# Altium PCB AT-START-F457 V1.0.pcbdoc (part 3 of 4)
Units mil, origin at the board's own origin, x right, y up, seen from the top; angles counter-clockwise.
Board outline 11593.57 x 3554 mil, 2 copper layers (Top Layer, Bottom Layer); 196 components, 231 nets, 905 pads, 932 vias.
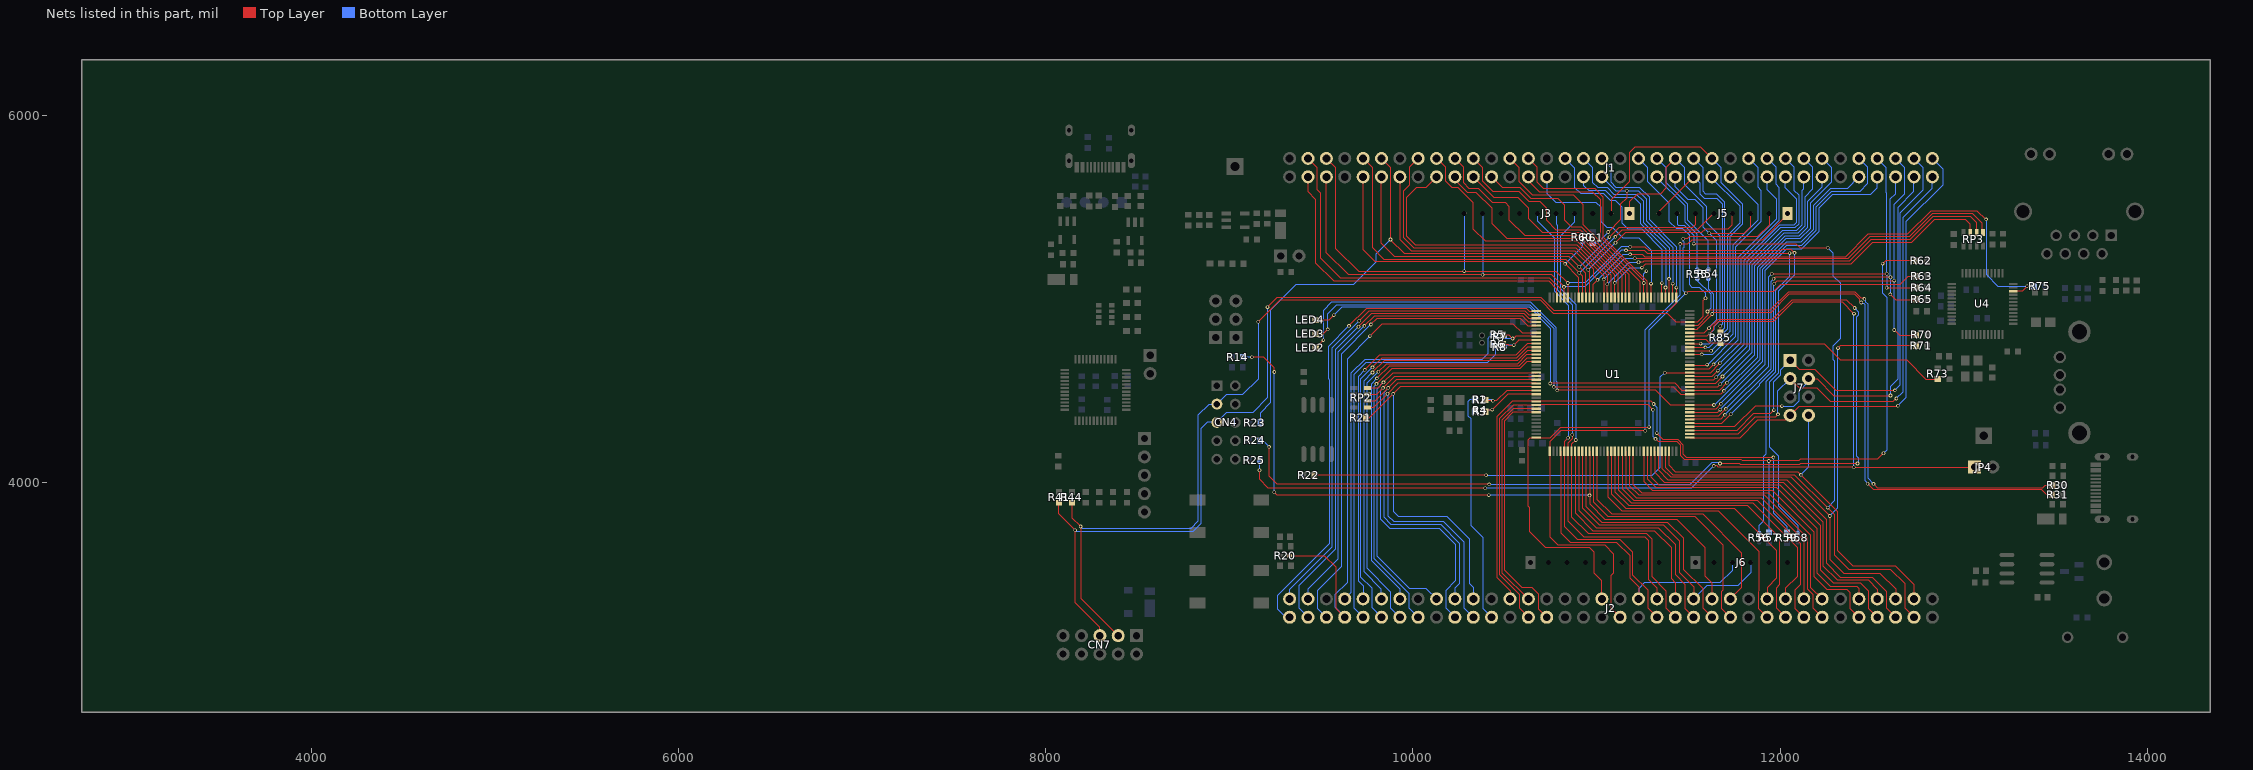
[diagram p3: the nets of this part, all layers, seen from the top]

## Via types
v1: diameter 19.7, hole 11.8, Top Layer to Bottom Layer, 489 vias
v2: diameter 19.68, hole 11.81, Top Layer to Bottom Layer, 425 vias
v3: diameter 31.5, hole 19.68, Top Layer to Bottom Layer, 18 vias

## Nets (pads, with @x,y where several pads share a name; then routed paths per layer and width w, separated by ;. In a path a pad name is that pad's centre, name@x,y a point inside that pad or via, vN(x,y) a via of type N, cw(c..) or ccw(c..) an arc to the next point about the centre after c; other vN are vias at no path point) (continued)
PA2: J2.36 J5.2 R63.1 U1.36 | length 4831.4
  Top Layer w6: J2.36@11029.17,3367.08 11029.16,3466.98 10988.26,3507.98 10988.26,3619.98 10962.26,3645.98 10723.16,3645.98 10637.36,3731.78 10637.36,3862.08 10628.51,3870.93 10628.51,4233.83 10640.16,4245.48 U1.36@10671.86,4245.5 10748.11,4245.48 10804.61,4301.98 11286.38,4301.98 v2(11286.92,4302.51) ; v2(11472.46,5327.97) 11493.46,5327.97 11504.98,5339.49 11876.37,5339.49 11939.76,5402.88 J5.2@11939.8,5465.97 ; v2(11487.2,5031.73) 11499.08,5043.61 11966.25,5043.61 12003.14,5080.5 12654.81,5080.5 12698.19,5123.88 R63.1@12741.42,5123.88
  Bottom Layer w6: v2(11286.92,4302.51) 11286.92,4832.35 11486.29,5031.73 v2(11487.2,5031.73) 11474.03,5044.89 11474.03,5279.85 11477.58,5283.4 11477.58,5308.44 11474.03,5311.99 11474.03,5326.4 v2(11472.46,5327.97)
PA3: J2.37 J5.1 U1.37 | length 3573.7
  Top Layer w6: J2.37@11129.17,3267.08 11078.26,3318.08 11078.26,3493.98 11092.26,3507.98 11092.26,3613.88 11043.96,3662.18 10789.96,3662.18 10745.76,3706.38 10745.76,4171.68 10745.76,4222.64 10805.43,4282.31 v2(11265.79,4282.31) ; v2@11455.95,5300.35 11497.63,5300.35 11520.43,5323.15 11904.31,5323.15 12039.76,5458.69 J5.1@12039.8,5465.97
  Bottom Layer w6: v2(11265.79,4282.31) 11265.79,4832.84 11456.7,5023.74 11456.7,5299.6 v2(11455.91,5300.39)
PA4: J2.40 J6.3 U1.40 | length 1779.9
  Top Layer w6: U1.40@10804.76,4171.68 10804.76,3728.38 10856.46,3676.68 11108.56,3676.68 11180.26,3604.98 11180.26,3481.18 11229.16,3432.28 J2.40@11229.17,3367.08
  Bottom Layer w6: J2.40@11229.17,3367.08 11229.16,3422.98 11260.26,3453.98 11672.26,3453.98 11739.86,3521.58 J6.3@11739.86,3565.98
PA5: J2.41 J3.6 U1.41 | length 2624.8
  Top Layer w6: v2(10845.74,4244.57) 10845.74,4243.88 10824.46,4222.6 10824.46,4171.68 10824.46,3761.68 10895.26,3690.98 11128.16,3690.98 11196.26,3622.98 11196.26,3497.98 11278.26,3415.98 11278.26,3318.08 J2.41@11329.17,3267.08
  Bottom Layer w6: J3.6@10679.86,5465.98 10679.86,5424.38 10772.26,5331.98 10772.26,5041.78 10849.23,4964.8 10849.23,4248.06 v2(10845.74,4244.57)
PA6: J2.42 J3.5 U1.42 | length 2540.2
  Top Layer w6: v2(10868.07,4261.17) 10868.07,4238.25 10844.16,4214.33 10844.16,4171.68 10844.16,3792.98 10931.26,3705.98 11262.26,3705.98 11282.26,3685.98 11282.26,3474.88 11329.16,3427.98 J2.42@11329.17,3367.08
  Bottom Layer w6: J3.5@10779.86,5465.98 10779.86,5409.38 10787.26,5401.98 10787.26,5049.37 10868.07,4968.55 v2(10868.07,4261.17)
PA7: J2.43 J3.4 U1.43 | length 2695.5
  Top Layer w6: v2(10886.92,4232.13) 10886.38,4232.13 10863.86,4209.61 10863.86,4171.68 10863.86,3814.88 10954.76,3723.98 11271.26,3723.98 11300.26,3694.98 11300.26,3489.98 11378.26,3411.98 11378.26,3318.08 J2.43@11429.17,3267.08
  Bottom Layer w6: J3.4@10879.86,5465.98 10879.86,5419.38 10802.26,5341.78 10802.26,5057.48 10886.92,4972.82 v2(10886.92,4232.13)
PA8: R73.1 R85.2 U1.100 | length 1438.4
  Top Layer w6: U1.100@11508.56,4776.98 11598.72,4776.98 11616.38,4759.32 R85.2@11675.37,4759.32 11678.8,4755.88 12240.28,4755.88 12327.55,4668.61 12688.93,4668.61 12793.39,4564.15 R73.1@12858.77,4564.15
PA8_E: J1.28 J5.8 R85.1 | length 1234.4
  Top Layer w6: J5.8@11339.8,5465.97 11339.76,5476.28 J1.28@11529.16,5665.68 ; v2(11674.65,4852.07) 11674.65,4819.36 R85.1@11675.37,4818.64
  Bottom Layer w6: J1.28@11529.16,5665.68 11562.68,5632.15 11562.68,5573.01 11585.76,5549.98 11654.26,5549.98 11684.86,5519.38 11684.86,4862.28 v2(11674.65,4852.07)
PA9: J1.29 J3.1 JP4.1 R25.2 U1.101 | length 7470.9
  Top Layer w6: v2@9165.26,4067.98 9165.26,4017.48 9213.04,3969.7 v2(10394.29,3969.7) ; J3.1@11179.86,5465.98 11179.86,5529.58 11222.26,5571.98 11346.26,5571.98 11378.26,5603.98 11378.26,5714.68 J1.29@11429.16,5765.68 ; U1.101@11508.56,4796.68 11601.67,4796.68 v2(11616.51,4811.52) 11637.11,4832.12 11637.11,4848.16 11664.43,4875.48 11962.39,4875.48 12069.05,4982.14 12340.98,4982.14 v2(12402.52,4920.6) ; v2(11638.56,4091.12) 11657.79,4091.12 11664,4084.9 12097.95,4084.9 12098.24,4084.61 12402.59,4084.61 v1(12401.55,4083.57) 13057.26,4083.57 JP4.1@13058.9,4085.21
  Bottom Layer w5.98: v2(11616.51,4811.52) 11637.75,4832.76
  Bottom Layer w6: R25.2@9165.16,4123.08 9165.16,4068.18 v2@9165.26,4067.98 ; v2(10394.29,3969.7) 11517.14,3969.7 v2(11638.56,4091.12) ; J1.29@11429.16,5765.68 11430.23,5765.68 11478.47,5717.43 11478.47,5625.23 11598.47,5505.23 11598.47,5417.73 11670.47,5345.73 11670.47,4881.96 11637.75,4849.24 11637.75,4832.76 ; v1(12401.55,4083.57) 12401.6,4919.67 v2(12402.52,4920.6)
  other v2: 9165.21,4067.97
PA10: J1.30 J5.3 R24.2 U1.102 | length 6628.5
  Top Layer w5.98: v2(11672.93,4104.54) 11778.61,4104.54 11784.06,4099.09
  Top Layer w6: v2(9217.21,4194.97) 9217.21,4034.97 9261.35,3990.83 v2(10415.89,3990.83) ; U1.102@11508.56,4816.38 11588.38,4816.38 v2(11612.86,4840.85) 11659.48,4887.48 11955.7,4887.48 12062.26,4994.12 12363.24,4994.12 v2(12406.02,4951.35) ; v2(11614.7,5358.7) 11803.86,5358.68 11839.76,5394.68 J5.3@11839.8,5465.97 ; 11784.06,4099.09 12106.71,4099.09 12112.23,4104.61 v1(12421.75,4104.61)
  Bottom Layer w6: R24.2@9165.76,4229.98 9182.16,4229.98 v2@9217.26,4194.98 ; v2(10415.89,3990.83) 11510.33,3990.83 11630.02,4110.51 11666.95,4110.51 v2(11672.93,4104.54) ; J1.30@11429.16,5665.68 11429.16,5612.78 11501.26,5540.78 11537.86,5540.78 11581.56,5496.98 11581.56,5391.78 v2(11614.7,5358.7) ; v2(11612.86,4840.85) 11612.86,4843.5 11655.27,4885.91 11655.27,5318.12 v2(11614.7,5358.7) ; v2(12406.02,4951.35) 12425.85,4931.51 12425.85,4911.76 12415.25,4901.16 12415.25,4147.35 12425.85,4136.75 12425.85,4108.71 v1(12421.75,4104.61)
PA11: R31.1 R54.2 U1.103 | length 3282.1
  Top Layer w5.98: v2(12476.65,3994.46) 12510.5,3960.61 13424.57,3960.61 13451.57,3933.61 R31.1@13481.91,3933.61
  Top Layer w6: U1.103@11508.48,4836.05 11548.07,4836.05 11555.72,4843.7 11555.94,4843.7 11616.54,4904.3 11616.54,4904.52 v2(11630.42,4918.4) 11638.33,4926.31 11948.84,4926.31 12047.91,5025.38 12406.09,5025.38 12433.82,4997.65 12433.82,4989.16 v2@12441.74,4981.24
  Bottom Layer w6: R54.2@11609.4,5114.26 11609.4,5057.08 11636.57,5029.91 11636.57,4924.55 v2(11630.42,4918.4) ; v2(12441.7,4981.25) 12447.61,4975.34 12457.29,4975.34 12464.22,4968.4 12464.22,4009.93 12476.65,3997.5 v2(12476.65,3994.46)
PA11_E: J1.31 R54.1 | length 726
  Bottom Layer w6: J1.31@11329.16,5765.68 11380.26,5714.58 11380.26,5633.98 11497.66,5516.58 11497.66,5429.28 11608.26,5318.68 R54.1@11608.26,5155.28
PA12: R30.1 R55.2 U1.104 | length 3293.1
  Top Layer w5.98: U1.104@11508.56,4855.68 11550.98,4855.68 11604.56,4909.27 11604.56,4909.48 11604.85,4909.76 v2(11604.85,4932.15) ; v2(12508.84,3993.3) 12529.56,3972.58 13431.54,3972.58 13444.57,3985.61 R30.1@13482.91,3985.61
  Top Layer w6: v2(11604.85,4932.15) 11612.01,4939.31 11944.9,4939.31 12043.64,5038.06 12410.38,5038.06 12443.15,5005.29 12454.65,5005.29 v2@12459.03,5000.9
  Bottom Layer w6: R55.2@11549.03,5099.37 R55.2@11549.03,5100.5 ; R55.2@11549.03,5113.47 R55.2@11549.03,5100.5 ; v2(11604.85,4932.15) 11624.58,4951.89 11624.58,5024.95 R55.2@11549.03,5100.5 ; v2(12459.03,5000.95) 12465.03,4994.95 12465.03,4984.56 12476.22,4973.37 12476.22,4025.51 12508.43,3993.3 v2(12508.84,3993.3)
PA12_E: J1.32 R55.1 | length 601.9
  Bottom Layer w6: J1.32@11329.16,5665.68 11329.16,5660.98 11483.06,5507.08 11483.06,5418.98 11550.16,5351.88 R55.1@11550.16,5155.28
PA13/SWDIO: CN4.3 CN7.3 J1.33 R44.2 U1.105 | length 6379.1
  Top Layer w6: R44.2@8144.46,3888.68 8144.46,3807.38 v2(8190.46,3761.38) 8190.46,3371.66 CN7.3@8395.46,3166.58 ; v2@9158.26,4875.98 9277.17,4994.9 10692.84,4994.9 10764.76,4922.98 11385.27,4922.98 11432.77,4875.38 U1.105@11508.48,4875.42 11550.89,4875.38 11582.58,4907.07 11582.58,4992.55 v2(11593.93,5003.91)
  Bottom Layer w6: v2(8190.46,3761.38) 8199.22,3752.61 8793.57,3752.61 8832.26,3791.3 8832.26,4368.88 8891.53,4428.15 CN4.3@8933.23,4427.98 ; CN4.3@8933.26,4427.98 8970.96,4466.28 8983.16,4477.68 9072.16,4477.68 9158.26,4563.78 v2@9158.26,4875.98 ; J1.33@11229.16,5765.68 11280.26,5714.58 11280.26,5639.18 11397.56,5521.88 11397.56,5422.18 11436.26,5383.48 11470.86,5383.48 11506.76,5347.68 11506.76,5078.43 11522.46,5062.72 11563.62,5062.72 11593.93,5032.4 v2(11593.93,5003.91)
  other v2: 9158.21,4875.97
PA14/SWCLK: CN4.5 CN7.5 J1.37 R41.2 U1.109 | length 6292.3
  Top Layer w6: R41.2@8070.46,3888.68 8070.46,3830.78 v2(8160.56,3740.58) 8161.97,3739.27 8161.97,3346.21 8295.46,3212.73 CN7.5@8295.46,3166.58 ; v2@9208.26,4955.98 9259.16,5006.88 10699.46,5006.88 10771.36,4934.98 11393.48,4934.98 11434.66,4976.15 U1.109@11434.66,5008.31 11435.16,5008.78 v2(11435.21,5061.97)
  Bottom Layer w6: v2(8160.56,3740.58) 8168.52,3732.61 8801.57,3732.61 8845.26,3776.3 8845.26,4294.08 8879.26,4328.18 ; 8880.73,4327.97 CN4.5@8933.23,4327.98 8933.23,4330.45 8984.76,4381.98 9126.96,4381.98 9208.26,4463.28 v2@9208.26,4955.98 ; J1.37@11029.16,5765.68 11078.26,5716.58 11078.26,5637.88 11106.16,5609.98 11234.26,5609.98 11286.26,5557.98 11286.26,5434.58 11435.16,5285.68 v2(11435.21,5061.97)
  other v2: 9208.21,4955.97
PA15: J1.38 R61.1 U1.110 | length 1263.8
  Top Layer w6: v2(11063.88,5365.01) 11130.86,5431.98 11130.86,5515.88 11164.96,5550.08 v2(11165,5589.98) ; U1.110@11414.97,5008.31 11415.16,5008.48 v2(11415.21,5083.97)
  Bottom Layer w6: R61.1@10979.26,5307.48 11006.36,5307.48 v2(11063.88,5365.01) ; J1.38@11029.16,5665.68 11104.86,5589.98 v2(11165,5589.98) ; v2(11165,5589.98) 11226.26,5589.98 11270.26,5545.98 11270.26,5426.18 11415.16,5281.28 v2(11415.21,5083.97)
PB0: J2.46 J6.4 U1.46 | length 1685.8
  Top Layer w6: U1.46@10922.86,4171.68 10922.86,3862.28 11014.66,3770.48 11362.76,3770.48 11449.96,3683.28 11449.96,3513.18 11529.16,3434.08 J2.46@11529.17,3367.08
  Bottom Layer w6: J2.46@11529.17,3367.08 11600.06,3437.98 11768.26,3437.98 11839.86,3509.58 J6.4@11839.86,3565.98
PB1: J2.47 U1.47 | length 1397.4
  Top Layer w6: U1.47@10942.56,4171.68 10942.56,3872.88 11029.96,3785.48 11385.76,3785.48 11472.46,3698.78 11472.46,3529.78 11578.26,3423.98 11578.26,3318.08 J2.47@11629.17,3267.08
PB2/BOOT1: J2.48 R14.2 U1.48 | length 3908.9
  Top Layer w6: v2@9123.26,4682.98 9188.46,4682.98 9245.96,4625.48 v2@9245.96,4602.58 ; v2(9245.65,3947.99) 9261.67,3931.97 v2(10413.21,3931.97) ; U1.48@10962.26,4171.68 U1.48@10962.22,4171.68 v2(10962.21,3930.97) 10962.16,3883.98 11046.06,3800.08 11438.06,3800.08 11590.26,3647.88 11590.26,3493.88 11629.16,3454.98 J2.48@11629.17,3367.08
  Bottom Layer w6: R14.2@9072.76,4683.98 v2@9123.26,4682.98 ; v2(9245.65,3947.99) 9245.95,3948.29 v2(9245.95,4602.58) ; v2(10413.21,3931.97) 10414.21,3930.97 v2(10962.21,3930.97)
  other v2: 9123.21,4682.97
PB3: J1.61 J5.4 R23.2 U1.133 | length 4184.6
  Top Layer w6: J1.61@9829.16,5765.68 9878.26,5716.58 9878.26,5323.98 9952.26,5249.98 10865.2,5249.98 v2@10955.55,5159.63 ; v2@10955.56,5159.58 10962.26,5152.98 U1.133@10962.26,5008.28 ; v2(11103.68,5306.7) 11160.02,5363.04 11574.1,5363.04 11594.16,5383.18 11719.06,5383.18 11739.76,5403.78 J5.4@11739.8,5465.97
  Bottom Layer w6: R23.2@9167.76,4326.18 9167.66,4377.58 9223.86,4433.98 9223.86,4937.71 9363.38,5077.23 9676.13,5077.23 9798.08,5199.18 9798.08,5244 v2@9878.26,5324.18 ; v2@10955.55,5159.63 11102.62,5306.7 v2(11103.68,5306.7)
  other v2: 10955.55,5159.63 9878.21,5323.97
PB4: J1.62 J5.6 U1.134 | length 2465.4
  Top Layer w6: J1.62@9829.16,5665.68 9826.26,5662.68 9826.26,5305.98 9898.26,5233.98 10848.19,5233.98 v2(10906.68,5175.49) 10942.2,5139.97 ; 10942.16,5139.98 10942.16,5008.68 U1.134@10942.56,5008.28 ; v2(11070.58,5337.43) 11124.16,5390.98 11523.66,5390.98 11539.76,5407.08 J5.6@11539.8,5465.97
  Bottom Layer w6: v2(10906.68,5175.49) 10908.64,5175.49 v2(11070.58,5337.43)
PB5: J1.63 J5.5 U1.135 | length 2698.3
  Top Layer w6: J1.63@9729.16,5765.68 9778.26,5716.58 9778.26,5281.98 9842.26,5217.98 10831.74,5217.98 v2(10906.75,5143) 10922.86,5126.86 U1.135@10922.86,5008.28 ; v2(11102.89,5338.22) 11140.76,5376.08 11549.86,5376.08 J5.5@11639.8,5465.97
  Bottom Layer w6: v2(10906.75,5143) 10907.67,5143 v2(11102.89,5338.22)
PB6: J1.64 R60.2 U1.136 | length 1904.4
  Top Layer w6: J1.64@9729.16,5665.68 9729.16,5269.08 9796.26,5201.98 10818.5,5201.98 v2(10829.24,5191.23) 10903.16,5117.32 U1.136@10903.16,5008.31
  Bottom Layer w5.98: 10923.85,5285.84 R60.2@10923.85,5313.9
  Bottom Layer w6: v2(10829.24,5191.23) 10923.85,5285.84
PB8: J1.67 J3.10 R58.1 U1.139 | length 5231.9
  Top Layer w6: J1.67@9529.16,5765.18 9578.26,5716.58 9578.26,5277.88 9704.26,5151.98 v2(10280.21,5151.97) 10779.16,5151.98 v2@10843.52,5087.62 ; v2(10843.58,5087.62) 10843.56,5008.78 U1.139@10844.16,5008.18 ; v2@11184.27,5284.97 11264.36,5284.97 11284.65,5264.68 12003.86,5264.68 12010.9,5271.73 12058.02,5271.73 v2(12078.36,5251.39)
  Bottom Layer w5.98: v2(12078.36,5251.39) 12078.36,5130.48 11989.23,5041.35 11989.23,4595.16 11941.65,4547.59 11941.65,4194.26 11989.23,4146.69 11989.23,3874.73 12096.95,3767 R58.1@12096.95,3722.29
  Bottom Layer w6: J3.10@10279.86,5465.98 10279.86,5394.38 10280.16,5394.08 v2(10280.21,5151.97) ; v2(10843.58,5087.62) 10938.81,5087.62 11136.16,5284.98 v2@11184.26,5284.98
  other v2: 11184.21,5284.97
PB9: J1.68 J3.9 R56.1 U1.140 | length 5089.1
  Top Layer w6: J1.68@9529.16,5665.18 9529.16,5252.98 9650.26,5131.98 v2(10379.81,5131.97) 10757.26,5131.98 10823.26,5065.98 10823.26,5009.38 U1.140@10824.46,5008.18 ; v2(11161.21,5264.97) 11261.21,5264.97 11275.9,5250.28 v2(12051.95,5250.28)
  Bottom Layer w5.98: R56.1@11886.22,3723.08 11886.54,3723.4 11886.54,3768.6 11909.85,3791.92 11909.85,4142.52 11925.68,4158.34 11925.68,4552.87 11977.12,4604.31 11977.12,5048.7 12051.95,5123.53 v2(12051.95,5250.28)
  Bottom Layer w6: v2@10379.86,5131.98 J3.9@10379.86,5465.98 ; v2(10823.21,5065.97) 10937.34,5065.97 11136.34,5264.97 v2(11161.21,5264.97)
PB10: J2.69 J5.7 U1.69 | length 4423.2
  Top Layer w6: U1.69@11375.66,4171.68 11375.66,4085.08 11416.86,4043.98 12078.36,4043.98 v2@12258.76,3863.58 ; v2(11529.8,5301.63) 12086.6,5301.63 12109.27,5278.96 v2(12259.62,5278.96) ; v2(12259.51,3864.33) v2@12258.76,3863.58 ; J2.69@12729.17,3267.08 12678.26,3318.08 12678.26,3450.88 12600.66,3528.58 12373.6,3528.58 12293.72,3608.47 12293.72,3828.62 v2@12258.76,3863.58
  Bottom Layer w6: J5.7@11439.8,5465.97 11439.76,5407.48 11446.06,5401.28 11477.16,5401.28 11529.8,5348.64 v2(11529.8,5301.63) ; v2(12259.51,3864.33) 12295.87,3900.69 12295.87,4664.78 12287.41,4673.23 12287.41,4743.57 12326.75,4782.9 12326.75,5087.69 12287.41,5127.02 12287.41,5251.17 v2(12259.62,5278.96)
PB11: J2.70 J7.8 U1.70 | length 2245.9
  Top Layer w6: U1.70@11395.36,4171.68 11395.36,4094.98 11433.06,4057.28 11954.13,4057.28 11954.57,4057.72 12098.12,4057.72 ; v1(12113.57,4042.61) 12098.47,4057.72 12098.12,4057.72 ; J2.70@12729.17,3367.08 12729.16,3447.28 12627.76,3548.68 12395.86,3548.68 12312.19,3632.34 12312.19,3843.64 12098.12,4057.72
  Bottom Layer w6: v1(12113.57,4042.61) 12154.81,4083.85 J7.8@12154.81,4366.56
PB12: J1.1 J7.7 U1.73 | length 2676.8
  Top Layer w6: U1.73@11508.48,4245.5 11782.52,4245.5 11878.99,4341.98 12030.22,4341.98 J7.7@12054.81,4366.56 12104.86,4416.61 12639.57,4416.61 v1(12641.57,4418.61)
  Bottom Layer w6: v1(12641.57,4418.61) 12685.5,4462.54 12685.5,5419.63 12886.26,5620.48 12886.26,5708.58 J1.1@12829.16,5765.68
PB13: J1.2 J7.3 U1.74 | length 2671.3
  Top Layer w6: U1.74@11508.48,4265.19 11772.67,4265.19 11865.87,4358.39 11975.22,4358.39 v1(11988.45,4371.61) ; J7.3@12054.81,4566.56 12104.75,4516.61 12199.57,4516.61 12273.57,4442.61 12617.57,4442.61 v1(12633.57,4458.61)
  Bottom Layer w5.98: v1(11988.45,4371.61) 11988.45,4500.2 J7.3@12054.81,4566.56
  Bottom Layer w6: v1(12633.57,4458.61) 12670.36,4495.4 12670.36,5444.78 12829.16,5603.58 J1.2@12829.16,5665.68
PB14: J1.3 J7.1 U1.75 | length 2797.8
  Top Layer w6: U1.75@11508.48,4284.87 11765.61,4284.87 11857.95,4377.21 11948.58,4377.21 v1(11966.35,4394.98) ; J7.1@12054.81,4666.56 12104.75,4616.61 12189.83,4616.61 12303.83,4502.61 v1(12625.57,4502.61)
  Bottom Layer w6: v1(11966.35,4394.98) 11966.35,4550.36 12004.19,4588.19 12004.19,4615.55 12054.81,4666.17 J7.1@12054.81,4666.56 ; v1(12625.57,4502.61) 12655.22,4532.26 12655.22,5470.54 12779.26,5594.58 12779.26,5715.58 J1.3@12729.16,5765.68
PB15: J1.4 J7.4 U1.76 | length 2524
  Top Layer w6: U1.76@11508.48,4304.56 11751.22,4304.56 11863.52,4416.86 v1(12010.14,4416.86) ; J7.4@12154.81,4566.56 12201.62,4566.56 12293.57,4474.61 v1(12601.57,4474.61)
  Bottom Layer w6: v1(12010.14,4416.86) 12031.33,4416.86 12031.57,4416.61 12073.57,4416.61 12103.57,4446.61 12103.57,4498.61 12154.81,4549.85 J7.4@12154.81,4566.56 ; v1(12601.57,4474.61) 12601.57,4525.12 12642.56,4566.11 12642.56,5500.42 12729.16,5587.08 J1.4@12729.16,5665.68
PC0: J2.26 R59.1 U1.26 | length 3240.4
  Top Layer w6: J2.26@10529.17,3367.08 10530.26,3368.08 10530.26,3411.93 10458.26,3483.93 10458.26,4359.3 10541.23,4442.28 U1.26@10671.86,4442.35 11297.51,4442.28 v2(11311.47,4428.32) ; v2(11328.21,4269.97) 11328.21,4267.98 11359.92,4236.27 11441.97,4236.27 11470.48,4207.75 11470.48,4157.41 11489.79,4138.09 11962.99,4138.09 v2(11963.64,4137.44)
  Bottom Layer w6: v2(11311.47,4428.32) 11328.21,4411.59 v2(11328.21,4269.97) ; v2(11963.64,4137.44) 11963.64,3835.3 12037.06,3761.88 R59.1@12037.06,3729.62
PC1: J2.27 R57.1 R62.1 U1.27 | length 5163
  Top Layer w6: J2.27@10629.17,3267.08 10578.26,3318.08 10578.26,3391.93 10470.26,3499.93 10470.26,4347.3 10545.63,4422.68 U1.27@10671.86,4422.67 10672.26,4422.98 11281.24,4422.98 v2(11307.17,4397.05) ; v2(11321.68,4238.22) 11338.34,4221.56 11439.72,4221.56 11458.49,4202.79 11458.49,4146.15 11480.41,4124.23 11789.72,4124.23 11795.98,4117.98 v2(11938.17,4118) 12100.87,4117.98 12109.56,4126.67 12529.56,4126.67 v2(12563.05,4160.16) ; v2(12558.37,5193.11) 12574.35,5209.08 R62.1@12740.55,5209.08
  Bottom Layer w6: v2(11307.17,4397.05) 11307.21,4252.7 v2(11321.68,4238.22) ; v2(11938.17,4118) 11938.22,3729.42 R57.1@11940.16,3727.48 ; v2(12558.37,5193.11) 12558.37,5032.43 12582.74,5008.07 12582.74,4179.84 v2(12563.05,4160.16)
PC2: J2.28 U1.28 | length 1245.1
  Top Layer w6: J2.28@10629.1,3367.08 10485.57,3510.61 10485.57,4340.61 10547.93,4402.98 U1.28@10671.86,4402.98
PC3: J2.29 U1.29 | length 1390.1
  Top Layer w6: U1.29@10671.86,4383.3 10545.2,4383.28 10497.57,4335.64 10497.57,3526.61 10593.57,3430.61 10647.66,3430.61 10682.26,3395.89 10682.26,3314.08 J2.29@10729.17,3267.08
PC4: J2.44 U1.44 | length 1227.3
  Top Layer w6: U1.44@10883.56,4171.68 10883.56,3834.98 10979.56,3738.98 11315.26,3738.98 11406.26,3647.98 11406.26,3478.18 11429.36,3454.98 J2.44@11429.17,3367.08
PC5: J2.45 U1.45 | length 1362.3
  Top Layer w6: U1.45@10903.16,4171.68 10903.16,3850.38 10998.06,3755.48 11336.76,3755.48 11428.26,3663.98 11428.26,3499.98 11480.26,3447.98 11480.26,3316.08 J2.45@11529.17,3267.08
PC6: J1.24 U1.96 | length 1257.2
  Top Layer w6: U1.96@11508.56,4698.28 11573.58,4698.28 v2(11573.72,4698.36)
  Bottom Layer w6: v2(11573.72,4698.36) 11632.04,4698.37 11743.96,4810.29 11743.96,5294.78 11881.46,5432.28 11881.46,5513.38 J1.24@11729.16,5665.68
PC7: J1.25 J3.2 U1.97 | length 2167
  Top Layer w6: J3.2@11079.86,5465.98 11079.86,5539.58 11178.26,5637.98 11178.26,5797.98 11208.26,5827.98 11566.86,5827.98 J1.25@11629.16,5765.68 ; U1.97@11508.56,4717.88 11624.3,4717.88 v2(11624.54,4718.06)
  Bottom Layer w6: v2(11624.54,4718.06) 11729.76,4823.34 11729.76,5341.48 11797.56,5409.18 11797.56,5516.78 11680.26,5633.98 11680.26,5714.58 J1.25@11629.16,5765.68
PC8: J1.26 U1.98 | length 1168.5
  Top Layer w6: U1.98@11508.56,4737.58 11592.77,4737.58 v2(11593.42,4736.97)
  Bottom Layer w6: v2(11593.42,4736.97) 11614.7,4736.98 11715.16,4837.44 11715.16,5348.78 11782.96,5416.58 11782.96,5505.18 11629.16,5658.98 J1.26@11629.16,5665.68
PC9: J1.27 U1.99 | length 1255
  Top Layer w6: U1.99@11508.56,4757.28 11566.78,4757.28 v2(11567.02,4757.46)
  Bottom Layer w6: J1.27@11529.16,5765.68 11580.26,5714.58 11580.26,5586.18 11594.96,5571.48 11655.66,5571.48 11699.76,5527.38 11699.76,4844.1 11613.13,4757.47 v2(11567.02,4757.46)
PC10: J1.39 U1.111 | length 1052.5
  Top Layer w6: v2(11395.21,5109.97) 11395.16,5008.38 U1.111@11395.36,5008.28
  Bottom Layer w6: J1.39@10929.16,5765.68 10978.26,5716.58 10978.26,5635.98 11006.26,5607.98 11058.26,5607.98 11095.26,5570.98 11217.26,5570.98 11254.26,5533.98 11254.26,5418.88 11395.16,5278.08 v2(11395.21,5109.97)
PC11: J1.40 U1.112 | length 963.4
  Top Layer w6: U1.112@11375.66,5008.28 11376.16,5008.88 v2(11376.21,5062.97)
  Bottom Layer w6: J1.40@10929.16,5665.68 10929.16,5620.98 10958.26,5591.98 11048.16,5591.98 11086.16,5553.98 11202.16,5553.98 11238.16,5517.98 11238.16,5412.88 11376.16,5274.98 v2(11376.21,5062.97)
PC12: J1.41 U1.113 | length 1108.7
  Top Layer w6: U1.113@11355.96,5008.28 11356.16,5008.58 v2(11356.21,5086.97)
  Bottom Layer w6: J1.41@10829.16,5765.68 10880.26,5714.58 10880.26,5609.88 10914.26,5575.98 11037.26,5575.98 11074.26,5538.98 11103.26,5538.98 11138.26,5503.98 11138.26,5415.58 11170.66,5383.18 11245.56,5383.18 11356.16,5272.48 v2(11356.21,5086.97)
PC13: J2.7 R20.2 U1.7 | length 3158.1
  Top Layer w6: R20.2@9326.5,3602.96 9518.26,3602.98 9579.26,3541.98 9579.26,3317.08 J2.7@9629.17,3267.08 ; v2(9766.21,4797.97) 9834.76,4866.58 10545.36,4866.58 10595.56,4816.38 U1.7@10671.86,4816.37
  Bottom Layer w6: J2.7@9629.16,3267.18 9629.16,3270.98 9578.26,3322.18 9578.26,3391.88 9644.21,3457.83 9644.21,4675.97 v2(9766.21,4797.97)
PC14/LEXT_IN: R5.2 R7.2 U1.8 | length 243.7
  Top Layer w5.98: R5.2@10491.86,4805.92 10492.86,4804.92 10522.09,4804.92 10542.11,4784.91 v2(10543.11,4784.91)
  Top Layer w6: v2(10543.11,4784.91) 10549.25,4784.91 10561.02,4796.68 U1.8@10671.86,4796.68
  Bottom Layer w5.98: R7.2@10496.94,4794.53 10506.56,4784.91 v2(10543.11,4784.91)
PC14_E: J2.8 R7.1 | length 2162.5
  Bottom Layer w5.98: 10357.86,4670.38 10375.33,4670.38 10407.57,4702.61 10407.57,4784.61 10417.49,4794.53 R7.1@10452.54,4794.53
  Bottom Layer w6: J2.8@9629.16,3367.18 9662.26,3400.28 9662.26,4594.98 9737.66,4670.38 10357.86,4670.38
PC15/LEXT_OUT: R6.2 R8.2 U1.9 | length 252.8
  Top Layer w5.98: R6.2@10491.86,4753.19 10519.33,4753.19 10523.62,4748.9 v2(10549.85,4748.9)
  Top Layer w6: v2(10549.85,4748.9) 10576.52,4775.58 10576.52,4776.98 U1.9@10671.86,4777
  Bottom Layer w5.98: R8.2@10496.23,4737.01 10508.12,4748.9 v2(10549.85,4748.9)
PC15_E: J2.9 R8.1 | length 2197.4
  Bottom Layer w6: J2.9@9729.17,3267.08 9680.56,3315.68 9680.56,4590.78 9745.16,4655.38 10407.33,4655.38 10451.83,4699.88 R8.1@10451.83,4737.01
PD2: J1.44 U1.116 | length 1087.8
  Top Layer w6: U1.116@11296.86,5008.31 11297.16,5008.58 v2(11297.21,5083.97)
  Bottom Layer w6: J1.44@10729.16,5665.68 10729.16,5576.98 10778.26,5527.98 10996.26,5527.98 11022.26,5501.98 11022.26,5424.98 11056.76,5390.48 11086.76,5390.48 11144.26,5332.98 11229.06,5332.98 11297.16,5264.88 v2(11297.21,5083.97)
PD3: J1.45 U1.117 | length 1188.7
  Top Layer w6: J1.45@10629.18,5765.65 10678.21,5716.62 10678.21,5641.97 ; 10678.26,5641.98 10678.26,5635.88 10714.16,5599.98 10992.16,5599.98 11038.26,5553.98 11038.26,5336.98 11277.26,5097.88 U1.117@11277.26,5008.28
PD4: J1.46 U1.118 | length 1158.2
  Top Layer w6: J1.46@10629.16,5665.68 10629.16,5642.98 10690.16,5581.98 10980.26,5581.98 11022.26,5539.98 11022.26,5333.98 11257.56,5098.58 v2(11257.56,5087.45) U1.118@11257.56,5008.28
  Bottom Layer w6: v2(11257.56,5087.45) 11257.56,5137.32 v2(11272.21,5151.97)
PD5: J1.47 U1.119 | length 1182.1
  Top Layer w6: J1.47@10529.16,5765.68 10580.26,5714.58 10580.26,5637.98 10652.26,5565.98 10876.26,5565.98 10928.26,5513.98 10928.26,5404.98 11237.86,5095.28 U1.119@11237.86,5008.28
PD6: J1.50 U1.122 | length 1167.3
  Top Layer w6: J1.50@10429.16,5665.68 10488.86,5605.98 10584.26,5605.98 10644.26,5545.98 10792.26,5545.98 10828.26,5509.88 10828.26,5427.98 10864.26,5391.98 10920.26,5391.98 11178.76,5133.38 U1.122@11178.76,5008.28 ; J1.50@10429.18,5665.65 J1.50@10446.21,5648.62
PD7: J1.51 U1.123 | length 1298.3
  Top Layer w6: J1.51@10329.16,5765.68 10380.26,5714.58 10380.26,5640.58 10436.86,5583.98 10580.26,5583.98 10634.26,5529.98 10694.26,5529.98 10730.26,5493.98 10730.26,5427.88 10782.26,5375.98 10915.26,5375.98 11159.16,5131.98 U1.123@11159.16,5008.28
PD8: J1.5 R70.1 U1.77 | length 2827.3
  Top Layer w6: U1.77@11508.56,4324.18 11682.8,4324.18 v2(11731.4,4372.78) ; v2(11968.3,5083.41) 11982.4,5097.51 12618.89,5097.51 v2(12621.85,5100.47) ; v2(12621.66,4831.69) 12650.98,4802.38 R70.1@12745.26,4802.38
  Bottom Layer w6: v2(11731.4,4372.78) 11886.84,4528.22 11886.84,4535.88 11962.99,4612.03 11962.99,5078.1 v2(11968.3,5083.41) ; v2(12621.66,4831.69) 12621.66,5100.28 v2(12621.85,5100.47) 12621.85,5516 12680.07,5574.22 12680.07,5714.76 J1.5@12629.18,5765.65
PD9: J1.6 R65.1 U1.78 | length 2499.4
  Top Layer w6: U1.78@11508.56,4343.88 11513.4,4348.72 11678.8,4348.72 v2(11699.21,4369.13) ; v2(11964.62,5110.37) 11972.51,5118.27 v2(12601.15,5118.27) ; v2(12599.92,5025.61) 12629.7,4995.83 12738.27,4995.83 R65.1@12741.42,4998.98
  Bottom Layer w5.98: v2(12599.92,5025.61) 12601.15,5026.84 v2(12601.15,5118.27)
  Bottom Layer w6: v2(11699.21,4369.13) 11948.8,4618.73 11948.8,5094.56 v2(11964.62,5110.37) ; v2(12601.15,5118.27) 12601.15,5546.13 12629.18,5574.16 J1.6@12629.18,5665.65
PD10: J1.7 R64.1 U1.79 | length 2565.9
  Top Layer w6: U1.79@11508.56,4363.58 11667.03,4363.58 v2(11705.03,4401.58) ; v2(11954.33,5137.75) 11954.41,5137.83 v2(12580.97,5137.83) ; v2(12580.12,5061.68) 12581.26,5062.81 R64.1@12741.42,5062.81
  Bottom Layer w6: v2(11705.03,4401.58) 11935.41,4631.96 11935.41,5118.83 v2(11954.33,5137.75) ; J1.7@12529.18,5765.65 12579.2,5715.62 12579.2,5578.16 12580.97,5576.4 v2(12580.97,5137.83) 12580.97,5062.52 v2(12580.12,5061.68)
PD11: J1.8 U1.80 | length 1963.6
  Top Layer w6: U1.80@11508.56,4383.28 11659.95,4383.28 v2(11674.49,4397.82)
  Bottom Layer w6: v2(11674.49,4397.82) 11674.49,4399.67 11920.26,4645.44 11920.26,5155.98 12037.17,5272.9 12119.17,5272.9 12214.26,5367.98 12214.26,5497.98 12286.26,5569.98 12494.16,5569.98 12529.16,5604.98 J1.8@12529.16,5665.68
PD12: J1.9 U1.81 | length 2005.3
  Top Layer w6: U1.81@11508.56,4402.98 11651.11,4402.98 v2(11677.69,4429.56)
  Bottom Layer w6: v2(11677.69,4429.56) 11677.69,4432.67 11906.26,4661.23 11906.26,5161.98 12037.67,5293.4 12117.67,5293.4 12198.26,5373.98 12198.26,5503.98 12282.26,5587.98 12436.26,5587.98 12478.26,5629.98 12478.26,5716.58 J1.9@12429.16,5765.68
PD13: J1.10 LED2.2 U1.82 | length 4464
  Top Layer w6: LED2.2@9472.01,4735.2 9512.66,4775.88 v2(9512.71,4776.37) ; v2(10786.63,4502.66) 11323.49,4502.66 11403.47,4422.68 U1.82@11508.48,4422.67 11638.79,4422.68 v2(11639.34,4423.23)
  Bottom Layer w6: v2(9512.71,4776.37) 9512.66,4937.58 9556.73,4981.58 10642.76,4981.58 10781.27,4843.07 10781.27,4552.28 10786.63,4546.92 v2(10786.63,4502.66) ; v2(11639.34,4423.23) 11644.09,4423.23 11892.26,4671.39 11892.26,5167.98 12035.93,5311.65 12114.53,5311.65 12182.26,5379.38 12182.26,5509.98 12276.26,5603.98 12367.46,5603.98 J1.10@12429.16,5665.68
PD14: J1.13 LED3.2 U1.85 | length 4312
  Top Layer w6: LED3.2@9472.06,4810.18 9472.16,4810.28 9512.23,4810.28 v2(9536.57,4834.61) ; v2(10767.03,4521.5) 11418.64,4521.5 11458.46,4481.68 11508.56,4481.68 11508.56,4484.78 11679.06,4484.78 v2@11694.26,4499.98
  Bottom Layer w6: v2(9536.57,4834.61) 9535.73,4835.45 9535.73,4919.16 9586.16,4969.58 10637.79,4969.58 10767.26,4840.11 10767.26,4521.73 v2(10767.03,4521.5) ; v2@11694.26,4499.98 11878.26,4683.98 11878.26,5173.98 12034.11,5329.83 12111.01,5329.83 12166.26,5385.08 12166.26,5524.48 12280.26,5638.58 12280.26,5714.58 J1.13@12229.16,5765.68
  other v2: 11694.21,4499.97
PD15: J1.14 LED4.2 U1.86 | length 4058.2
  Top Layer w6: LED4.2@9472.06,4886.48 9543.43,4886.48 v2(9569.57,4912.61) ; v2(10748.42,4540.34) 11429.39,4540.34 11468.36,4501.38 11508.56,4501.38 11667.66,4501.38 v2(11710.21,4543.97) ; J1.14@12229.16,5640.68 J1.14@12229.16,5665.68
  Bottom Layer w6: v2(9569.57,4912.61) 9614.53,4957.58 10632.82,4957.58 10748.84,4841.56 10748.84,4540.77 v2(10748.42,4540.34) ; v2(11710.21,4543.97) 11862.26,4695.98 11862.26,5179.98 12027.91,5345.63 12105.11,5345.63 12150.76,5391.28 12150.76,5532.28 12229.16,5610.68 J1.14@12229.16,5665.68
PE0: J1.69 U1.141 | length 1994.3
  Top Layer w6: J1.69@9429.16,5765.18 9480.26,5714.58 9480.26,5593.88 9498.96,5575.18 9498.96,5221.28 9607.11,5113.13 10746.41,5113.13 10804.76,5054.78 U1.141@10804.76,5008.18
PE1: J1.70 U1.142 | length 1905
  Top Layer w6: J1.70@9429.16,5665.18 9429.16,5582.98 9470.26,5541.88 9470.26,5195.88 9570.67,5095.57 10742.37,5095.57 10785.06,5052.88 U1.142@10785.06,5008.18
PE2: J2.1 U1.1 | length 2861.3
  Top Layer w6: v2(9652.16,4853.98) 9748.26,4950.08 10618.26,4950.08 10633.96,4934.48 U1.1@10671.86,4934.48
  Bottom Layer w6: J2.1@9329.17,3267.08 9307.16,3267.08 9262.26,3311.98 9262.26,3383.98 9545.96,3667.68 9545.96,4561.18 9538.26,4568.78 9538.26,4740.08 v2(9652.16,4853.98)
PE3: J2.2 U1.2 | length 2667
  Top Layer w6: v2(9708.16,4881.98) 9762.56,4936.38 10610.76,4936.38 10632.36,4914.78 U1.2@10671.86,4914.79
  Bottom Layer w6: J2.2@9329.16,3367.18 9329.16,3419.48 9560.26,3650.58 9560.26,4734.08 v2(9708.16,4881.98)
PE4: J2.3 U1.3 | length 2747.9
  Top Layer w6: v2(9703.83,4849.3) 9777.11,4922.58 10603.26,4922.58 10630.76,4895.08 U1.3@10671.86,4895.11
  Bottom Layer w6: J2.3@9429.17,3267.08 9378.26,3318.08 9378.26,3437.48 9578.26,3637.48 9578.26,4723.73 v2(9703.83,4849.3)
PE5: J2.4 U1.4 | length 2586.6
  Top Layer w6: v2(9736.21,4853.97) 9791.36,4909.18 10595.36,4909.18 10629.16,4875.38 U1.4@10671.86,4875.42
  Bottom Layer w6: J2.4@9429.17,3367.08 9429.16,3421.38 9594.26,3586.48 9594.26,4711.98 v2(9736.21,4853.97)
PE6: J2.5 U1.5 | length 2664.6
  Top Layer w6: v2(9771.79,4861.65) 9805.52,4895.38 10585.96,4895.38 10625.66,4855.68 U1.5@10671.86,4855.74
  Bottom Layer w6: J2.5@9529.16,3267.18 9481.96,3314.38 9481.96,3415.25 9612.26,3545.55 9612.26,4702.12 v2(9771.79,4861.65)
PE7: J2.58 U1.58 | length 1605.7
  Top Layer w6: U1.58@11159.16,4171.68 11159.16,3975.88 11216.06,3918.98 11897.66,3918.98 12129.16,3687.48 J2.58@12129.17,3367.08
PE8: J2.59 U1.59 | length 1740.3
  Top Layer w6: U1.59@11178.76,4171.68 11178.76,3984.18 11229.96,3932.98 11913.96,3932.98 12147.96,3698.98 12147.96,3422.08 12178.26,3391.68 12178.26,3318.08 J2.59@12229.17,3267.08
PE9: J2.60 U1.60 | length 1635.5
  Top Layer w6: U1.60@11198.46,4171.68 11198.46,3992.68 11245.36,3945.78 11935.06,3945.78 12164.76,3716.08 12164.76,3431.48 J2.60@12229.17,3367.08
PE10: J2.63 U1.63 | length 1835.9
  Top Layer w6: U1.63@11257.56,4171.68 11257.56,4006.68 11304.26,3959.98 11956.66,3959.98 12183.66,3733.08 12183.66,3490.58 12254.26,3419.98 12363.16,3419.98 12380.26,3402.88 12380.26,3316.08 J2.63@12429.17,3267.08
PE11: J2.64 U1.64 | length 1749.5
  Top Layer w6: U1.64@11277.26,4171.68 11277.26,4020.88 11323.96,3974.18 11978.36,3974.18 12200.56,3751.98 12200.56,3508.18 12272.76,3435.98 12416.86,3435.98 12429.16,3423.68 J2.64@12429.17,3367.08
PE12: J2.65 U1.65 | length 1887.8
  Top Layer w6: U1.65@11296.86,4171.68 11296.86,4031.28 11339.76,3988.38 11998.46,3988.38 12217.86,3768.98 12217.86,3525.98 12288.86,3454.98 12437.26,3454.98 12480.26,3411.98 12480.26,3316.08 J2.65@12529.17,3267.08
PE13: J2.66 U1.66 | length 1784.8
  Top Layer w6: U1.66@11316.56,4171.68 11316.56,4056.58 11370.56,4002.58 12017.36,4002.58 12233.26,3786.68 12233.26,3546.78 12310.06,3469.98 12479.06,3469.98 12529.16,3419.88 J2.66@12529.17,3367.08
PE14: J2.67 U1.67 | length 1920.6
  Top Layer w6: U1.67@11336.26,4171.68 11336.26,4069.88 11389.36,4016.78 12035.46,4016.78 12250.66,3801.58 12250.66,3562.78 12327.46,3485.98 12501.66,3485.98 12578.26,3409.38 12578.26,3318.08 J2.67@12629.17,3267.08
PE15: J2.68 R71.1 U1.68 | length 3197.8
  Top Layer w6: U1.68@11355.96,4171.68 11355.96,4079.18 11404.26,4030.98 12058.51,4030.98 v2(12270.92,3818.57) 12270.92,3583.92 12347.96,3506.88 12544.16,3506.88 12629.16,3421.88 J2.68@12629.17,3367.08 ; v2(12315.18,4732.93) 12330.65,4748.4 12740.24,4748.4 R71.1@12742.66,4745.98
  Bottom Layer w6: v2(12270.92,3818.57) 12315.18,3862.83 v2(12315.18,4732.93)
PF0: J2.10 U1.10 | length 2266
  Top Layer w6: v2@9738.26,4613.98 9817.16,4692.88 10559.16,4692.88 10623.56,4757.28 U1.10@10671.86,4757.31
  Bottom Layer w6: J2.10@9729.26,3367.08 9729.26,3438.98 9702.26,3465.88 9702.26,4577.98 v2@9738.26,4613.98
  other v2: 9738.21,4613.97
PF1: J2.11 U1.11 | length 2370.2
  Top Layer w6: v2(9780.26,4627.98) 9830.56,4678.28 10562.56,4678.28 10621.86,4737.58 U1.11@10671.86,4737.63
  Bottom Layer w6: v2(9780.26,4627.98) 9717.36,4565.08 9717.36,3484.78 9778.26,3423.88 9778.26,3318.08 J2.11@9829.16,3267.18
PF2: J2.12 U1.12 | length 2230
  Top Layer w6: v2(9780.26,4599.98) 9844.36,4664.08 10568.36,4664.08 10622.16,4717.88 U1.12@10671.86,4717.94
  Bottom Layer w6: v2(9780.26,4599.98) 9736.26,4555.98 9736.26,3513.48 9829.16,3420.48 J2.12@9829.17,3367.08
PF3: J2.13 U1.13 | length 2334.4
  Top Layer w6: v2(9812.26,4603.98) 9856.96,4648.68 10571.76,4648.68 10621.36,4698.28 U1.13@10671.86,4698.26
  Bottom Layer w6: v2(9812.26,4603.98) 9751.26,4542.98 9751.26,3533.58 9880.26,3404.48 9880.26,3316.18 J2.13@9929.16,3267.18
PF4: J2.14 U1.14 | length 2192.5
  Top Layer w6: v2@9804.26,4567.98 9870.46,4634.18 10576.36,4634.18 10620.76,4678.58 U1.14@10671.86,4678.57
  Bottom Layer w6: v2@9804.26,4567.98 9772.26,4535.98 9772.26,3578.68 9929.16,3421.78 J2.14@9929.16,3367.18
  other v2: 9804.21,4567.97
PF5: J2.15 U1.15 | length 2295.9
  Top Layer w6: v2(9802.21,4537.97) 9884.16,4619.98 10582.26,4619.98 10621.16,4658.88 U1.15@10671.86,4658.89
  Bottom Layer w6: v2(9802.21,4537.97) 9788.26,4523.18 9788.26,3587.98 9978.26,3397.88 9978.26,3318.08 J2.15@10029.17,3267.08
PF6: J2.18 RP2.4 U1.18 | length 2334.4
  Top Layer w6: RP2.4@9753.18,4516.15 9810.38,4516.15 v2(9840.21,4545.97) 9894.02,4599.78 U1.18@10671.86,4599.83
  Bottom Layer w6: v2(9840.21,4545.97) 9804.26,4509.98 9804.26,3601.88 9980.26,3425.88 10070.36,3425.88 J2.18@10129.16,3367.18
PF7: J2.19 RP2.3 U1.19 | length 2587.3
  Top Layer w6: RP2.3@9753.77,4480.48 cw(c9753.77,4481.3) RP2.3@9753.18,4480.72 9802.95,4480.72 v2(9838.21,4515.97) cw(c9838.28,4515.97) v2(9838.21,4515.97) 9861,4538.79 9902.37,4580.16 U1.19@10671.86,4580.18 ; 9960.77,4580.16 cw(c9960.77,4580.09) 9960.82,4580.14
  Bottom Layer w6: v2@9838.26,4515.98 9822.26,4499.98 9822.26,3803.88 9874.56,3751.58 10145.06,3751.58 10231.76,3664.88 10231.76,3464.78 10178.26,3411.28 10178.26,3318.08 J2.19@10229.16,3267.18
PF8: J2.20 RP2.2 U1.20 | length 2467.4
  Top Layer w6: RP2.2@9754.46,4445.81 ccw(c9754.46,4444.01) RP2.2@9753.18,4445.28 9795.51,4445.28 v2(9866.21,4515.97) 9910.7,4560.46 U1.20@10671.86,4560.46
  Bottom Layer w6: v2(9866.21,4515.97) 9840.26,4489.98 9840.26,3813.88 9880.26,3773.98 10150.66,3773.98 10253.86,3670.78 10253.86,3449.38 10229.16,3424.68 J2.20@10229.17,3367.08
PF9: J2.21 RP2.1 U1.21 | length 2542.3
  Top Layer w6: RP2.1@9753.89,4409.56 cw(c9753.89,4410.55) RP2.1@9753.18,4409.85 9788.08,4409.85 v2(9862.21,4483.97) 9919.02,4540.78 U1.21@10671.86,4540.78
  Bottom Layer w6: v2(9862.21,4483.97) 9864.26,4481.88 9864.26,3820.78 9896.06,3788.98 10166.36,3788.98 10276.26,3679.08 10276.26,3320.08 J2.21@10329.17,3267.08
PF10: J2.22 R21.1 U1.22 | length 2450
  Top Layer w6: R21.1@9744.84,4353.85 9763.43,4353.85 v2(9893.22,4483.63) 9930.67,4521.08 U1.22@10671.86,4521.09 ; v2@9899.22,4483.63 cw(c9900.17,4483.63) v2@9899.5,4484.31
  Bottom Layer w6: v2(9893.22,4483.63) 9893.22,3843.86 9920.1,3816.98 10186.05,3816.98 10307.4,3695.63 10307.4,3451.35 10329.18,3429.57 J2.22@10329.17,3367.08
PF11: J2.49 U1.49 | length 1497.2
  Top Layer w6: U1.49@10981.96,4171.68 10981.96,3896.18 11062.36,3815.78 11534.46,3815.78 11688.26,3661.98 11688.26,3413.98 11680.26,3405.98 11680.26,3316.08 J2.49@11729.17,3267.08
PF12: J2.50 U1.50 | length 1445.9
  Top Layer w6: U1.50@11001.66,4171.68 11001.66,3910.68 11081.96,3830.38 11577.96,3830.38 11788.86,3619.48 11788.86,3426.78 J2.50@11729.17,3367.08
PF13: J2.53 U1.53 | length 1575.8
  Top Layer w6: U1.53@11060.66,4171.68 11060.66,3924.48 11138.96,3846.18 11664.56,3846.18 11884.56,3626.18 11884.56,3409.98 11880.26,3405.68 11880.26,3316.08 J2.53@11929.17,3267.08
PF14: J2.54 U1.54 | length 1544.8
  Top Layer w6: U1.54@11080.36,4171.68 11080.36,3940.78 11160.06,3861.08 11751.16,3861.08 11980.26,3631.98 11980.26,3478.88 11929.16,3427.78 J2.54@11929.17,3367.08
PF15: J2.55 U1.55 | length 1683.1
  Top Layer w6: U1.55@11100.06,4171.68 11100.06,3951.08 11175.46,3875.68 11822.06,3875.68 11996.26,3701.48 11996.26,3442.88 11978.26,3424.88 11978.26,3318.08 J2.55@12029.17,3267.08
PG0: J2.56 U1.56 | length 1620.4
  Top Layer w6: U1.56@11119.76,4171.68 11119.76,3960.88 11190.36,3890.28 11850.66,3890.28 12092.26,3648.68 12092.26,3488.38 12029.16,3425.28 J2.56@12029.17,3367.08
PG1: J2.57 U1.57 | length 1733
  Top Layer w6: U1.57@11139.46,4171.68 11139.46,3967.48 11202.06,3904.98 11874.96,3904.98 12109.56,3670.38 12109.56,3443.88 12080.26,3414.58 12080.26,3316.08 J2.57@12129.17,3267.08
PG2: J1.15 U1.87 | length 1675.9
  Top Layer w6: U1.87@11508.56,4521.08 11659.26,4521.08 v2@11674.26,4535.98
  Bottom Layer w6: v2@11674.26,4535.98 11848.26,4709.98 11848.26,5187.98 12021.92,5361.64 12099.12,5361.64 12136.26,5398.78 12136.26,5557.98 12178.26,5599.98 12178.26,5716.58 J1.15@12129.16,5765.68
  other v2: 11674.21,4535.97
PG3: J1.16 U1.88 | length 1509.4
  Top Layer w6: U1.88@11508.56,4540.78 11648.96,4540.78 v2(11686.21,4577.97)
  Bottom Layer w6: v2(11686.21,4577.97) 11834.26,4725.98 11834.26,5195.98 12014.23,5375.95 12091.33,5375.95 12120.26,5404.88 12120.26,5592.08 12129.16,5600.98 J1.16@12129.16,5665.68
PG4: J1.17 U1.89 | length 1605.8
  Top Layer w6: U1.89@11508.56,4560.48 11638.66,4560.48 v2(11652.21,4573.97)
  Bottom Layer w6: v2(11652.21,4573.97) 11820.26,4741.98 11820.26,5205.98 12004.11,5389.83 12083.51,5389.83 12104.26,5410.58 12104.26,5563.98 12078.26,5589.98 12078.26,5716.58 J1.17@12029.16,5765.68
PG5: J1.18 U1.90 | length 1469.5
  Top Layer w6: U1.90@11508.56,4580.08 11630.36,4580.08 v2(11660.21,4609.97)
  Bottom Layer w6: v2(11660.21,4609.97) 11804.26,4753.98 11804.26,5209.98 11998.52,5404.24 12077.45,5404.24 12090.26,5416.98 12090.26,5543.98 12029.16,5604.98 J1.18@12029.16,5665.68
PG6: J1.19 R22.1 U1.91 | length 4029.8
  Top Layer w6: R22.1@9460.96,4039.98 v2@10399.26,4039.98 ; v2@11371.57,4598.69 11507.47,4598.69 11508.56,4599.78 11622.06,4599.78 v2(11672.21,4649.97)
  Bottom Layer w6: v2@10399.26,4039.98 11304.93,4039.98 11348.69,4083.74 11348.69,4575.74 v2(11371.57,4598.61) ; v2(11672.21,4649.97) 11788.26,4765.98 11788.26,5219.98 11996.26,5427.98 11996.26,5605.98 11978.26,5623.98 11978.26,5716.58 J1.19@11929.16,5765.68
  other v2: 10399.21,4039.97
PG7: J1.20 U1.92 | length 1326
  Top Layer w6: U1.92@11508.56,4619.48 11613.76,4619.48 v2@11638.26,4643.98
  Bottom Layer w6: v2@11638.26,4643.98 11773.46,4779.18 11773.46,5227.18 11982.26,5435.98 11982.26,5542.78 11929.16,5595.88 J1.20@11929.16,5665.68
  other v2: 11638.21,4643.97
PG8: J1.21 U1.93 | length 1370
  Top Layer w6: U1.93@11508.56,4639.18 11599.19,4639.18 v2@11602.82,4642.82
  Bottom Layer w6: v2@11602.82,4642.82 11605.09,4642.82 11758.86,4796.58 11758.86,5286.14 11897.16,5424.44 11897.16,5590.78 11880.26,5607.68 11880.26,5714.58 J1.21@11829.16,5765.68
  other v2: 11602.87,4642.81
PG9: J1.52 U1.124 | length 1212.9
  Top Layer w6: J1.52@10329.16,5665.68 10442.86,5551.98 10574.16,5551.98 10632.26,5493.88 10632.26,5435.98 10708.26,5359.98 10911.16,5359.98 11139.46,5131.68 U1.124@11139.46,5008.28 ; J1.52@10329.18,5665.65 J1.52@10346.21,5648.62
PG10: J1.53 U1.125 | length 1371.6
  Top Layer w6: J1.53@10229.16,5765.68 10276.26,5718.58 10276.26,5631.98 10308.26,5599.98 10358.26,5599.98 10434.26,5523.98 10506.16,5523.98 10526.26,5503.98 10526.26,5429.18 10611.36,5343.98 10908.16,5343.98 11119.76,5132.38 U1.125@11119.76,5008.28
PG11: J1.54 RP3.3 U1.126 | length 3408.6
  Top Layer w6: J1.54@10229.16,5665.68 10229.16,5648.98 10298.16,5579.98 10346.26,5579.98 10432.26,5493.98 10432.26,5409.98 10514.26,5327.98 10903.29,5327.98 11099.21,5132.06 v2(11099.21,5087.97) ; v2@11099.26,5087.98 11099.26,5009.18 U1.126@11100.06,5008.28 ; v2(11247.21,5170.97) 11266.27,5190.09 12385.01,5190.09 12502.1,5307.18 12713.51,5307.18 12838.32,5431.99 13011.03,5431.99 13035.36,5407.66 RP3.3@13035.36,5361.98
  Bottom Layer w6: v2(11099.21,5087.97) 11182.21,5170.97 v2(11247.21,5170.97)
PG12: J1.55 U1.127 | length 1463.6
  Top Layer w6: J1.55@10129.16,5765.68 10178.26,5716.58 10178.26,5641.98 10214.26,5605.98 10248.26,5605.98 10330.26,5523.98 10330.26,5379.98 10396.26,5313.98 10895.26,5313.98 11080.36,5128.78 U1.127@11080.36,5008.28
PG13: J1.56 RP3.2 U1.128 | length 3954.6
  Top Layer w6: J1.56@10129.16,5665.68 10069.46,5605.98 10018.26,5605.98 9964.26,5551.98 9964.26,5345.98 10014.27,5295.97 10893.3,5295.97 11059.21,5130.06 v2(11059.21,5080.97) ; v2@11059.26,5080.98 11059.26,5009.78 U1.128@11060.66,5008.28 ; v2(11229.21,5199.97) 11250.92,5199.97 11256.92,5205.97 12377.22,5205.97 12494.77,5323.52 12706.76,5323.52 12831.28,5447.96 13037.28,5447.96 13070.76,5414.37 RP3.2@13070.78,5361.97
  Bottom Layer w6: v2(11059.21,5080.97) 11178.21,5199.97 v2(11229.21,5199.97)
PG14: J1.57 RP3.1 U1.129 | length 4048.5
  Top Layer w6: J1.57@10029.16,5765.68 9980.26,5716.68 9980.26,5619.98 9948.26,5587.98 9948.26,5335.68 10003.96,5279.98 10888.06,5279.98 11039.86,5128.18 11039.86,5106.98 11039.86,5009.38 U1.129@11040.96,5008.31 ; v2@11208.26,5221.98 11211.44,5218.8 12368.38,5218.8 12489.44,5339.86 12702.3,5339.86 12827.92,5465.48 13048.46,5465.48 13102.26,5411.68 13102.26,5365.98 RP3.1@13106.21,5361.97
  Bottom Layer w6: v2@11039.86,5106.98 11154.86,5221.98 v2@11208.26,5221.98
  other v2: 11039.85,5106.94 11208.21,5221.97
PG15: J1.60 R75.1 U1.132 U4.10 | length 4614
  Top Layer w5.98: v2@11183.27,5242.97 11250.2,5242.97
  Top Layer w6: J1.60@9929.16,5665.68 9929.16,5326.98 9992.26,5263.98 10882.26,5263.98 10982.58,5163.66 10982.58,5127.91 v2(11006.06,5104.43) 10981.96,5080.32 U1.132@10981.96,5008.28 ; 11250.2,5242.97 11262.39,5230.78 12356.72,5230.78 12481.18,5355.24 12695.89,5355.24 12822.71,5482.06 13072.07,5482.06 13120.56,5433.56 v2(13122.14,5433.56) ; U4.10@13269.56,5042.88 13318.16,5042.88 v2@13345.26,5069.98
  Bottom Layer w6: v2(11006.06,5104.43) 11144.61,5242.97 v2(11183.21,5242.97) ; v2@13122.19,5433.57 13122.19,5134.05 13186.26,5069.98 13345.26,5069.98 R75.1@13385.76,5069.98
  other v2: 13345.21,5069.97
PH0/HEXT_IN: R1.2 R2.2 U1.23 | length 357.4
  Top Layer w6: R1.2@10387.76,4447.98 10389.56,4446.18 v2(10435.86,4446.18) 10455.13,4446.18 10510.33,4501.38 U1.23@10671.86,4501.41
  Bottom Layer w6: R2.2@10388.85,4452.62 10429.42,4452.62 v2(10435.86,4446.18)
PH0_E: J2.23 R2.1 | length 1278.9
  Bottom Layer w6: R2.1@10344.45,4452.62 10309.57,4452.62 10298.76,4441.8 10298.76,4365.43 10314.46,4349.73 10314.46,3767.38 10379.46,3702.28 10379.46,3316.78 J2.23@10429.17,3267.08
PH1/HEXT_OUT: R3.2 R4.2 U1.24 | length 365.2
  Top Layer w6: R3.2@10387.76,4393.98 10428.26,4393.98 v2(10432.26,4397.98) 10515.96,4481.68 U1.24@10671.86,4481.72
  Bottom Layer w6: R4.2@10388.85,4394.62 10428.9,4394.62 v2(10432.26,4397.98)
